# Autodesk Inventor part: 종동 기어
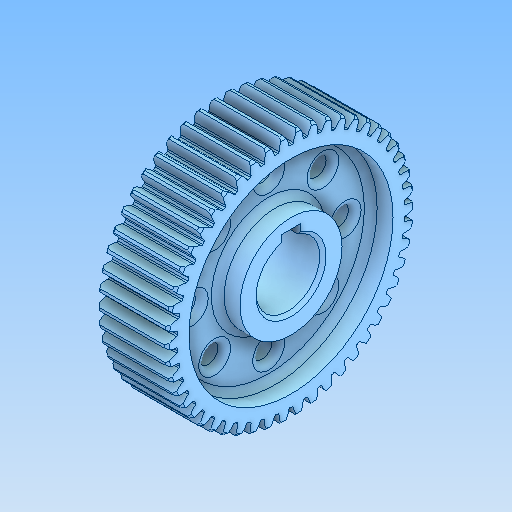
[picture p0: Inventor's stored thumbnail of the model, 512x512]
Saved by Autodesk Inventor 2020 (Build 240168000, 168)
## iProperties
Created: 2025-11
Part Number: 종동 기어
Material: 강철, 탄소
Document SubType Name: Modeling
Designer: PC2-06
Density: 7.85 g/cm^3
Appearance: 기본값
Author: jhkim
Sending System: Autodesk Inventor 2026
Preprocessor: ST-DEVELOPER v20.1
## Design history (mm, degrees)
feature "솔리드1"
node "솔리드2"
